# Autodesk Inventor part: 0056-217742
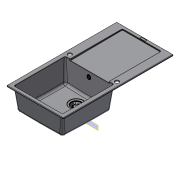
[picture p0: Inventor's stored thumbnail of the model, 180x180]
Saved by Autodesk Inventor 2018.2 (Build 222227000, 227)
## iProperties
Created: 2015-04
Part Number: 0056-217742
Material: EN 1.4301
Document SubType Name: Modeling
Density: 8.03 g/cm^3
Appearance: Steel
Description: MRG 611-97
Mass: 51972.3 g
Surface Area: 16879.2 cm^2
Volume: 6472.27 cm^3
Drawn_Date: 2017-11-15
Departement: Colored Sinks
Project: Sales Documents
Collection: 3D Data
Category: CAD-Models
Document_Number: 20127597
Title: MRG 611-97
Auxiliary_Remark1: 3D Data
Weight: 51.974
Drawn_By: AM049
CAXDisplayName: 0056-217742 - MRG 611-97 -
Mass_Unit: kg
Surface: 16879.241
cm cm cm: 6472.444
SAP_DESCRIPTION: MRG 611-97
SAP_DOCID: 20127597
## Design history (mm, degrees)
derived "20127596_1__MRG 611-97.iam"
body "Solid1"
workplane "Work Plane5"
node "20117584_1_112.0332.278_Stösselventil (VU):1::20117572_2__wa"
node "20117828_5_133.0433.420_Winkelrohr 97/117:1"
node "20118100_4__Raumspar-Teleskoprohr:1"
node "20117868_2__Überlaufkopf:1"
node "20117891_5__Überlaufeinsatz:1"
node "20117848_1__Dichtung:1"
node "20117806_1__Adapterring:1"
node "20117894_2__Logoplatte rund:1"
node "20109846_1__MRG 611-97:1"
